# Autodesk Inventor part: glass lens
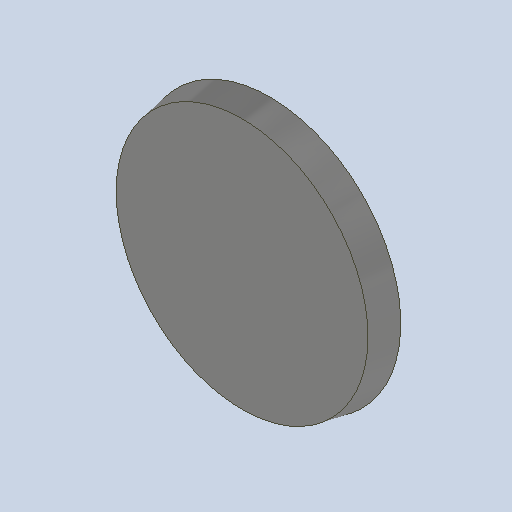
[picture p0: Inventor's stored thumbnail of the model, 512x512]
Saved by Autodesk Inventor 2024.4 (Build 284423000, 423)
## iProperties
Created: 2025-04
Part Number: glass lens
Material: Generic
Document SubType Name: Modeling
Designer: AdminForWorker
Density: 1 g/cm^3
Appearance: Default
Title: glass lens v2
Author: AdminForWorker
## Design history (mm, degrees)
feature "Body1"
body "Solid1"
